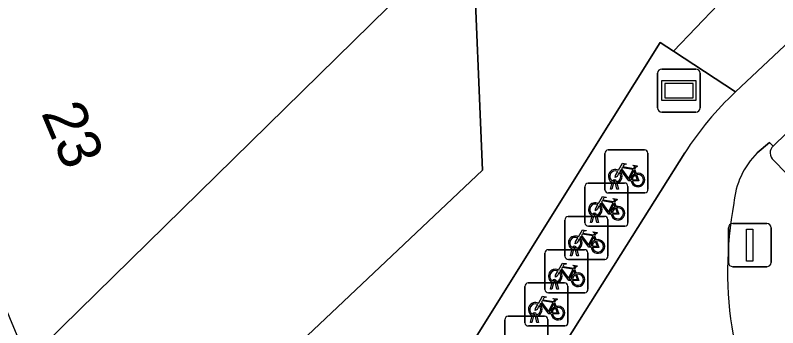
# Model space of a CAD drawing. Extents: x 160663 to 161506, y 382245 to 383291.
# Drawn here: x 161140.59 to 161158.3, y 383139.69 to 383146.96 of the extents above; entities that cross this region are included whole.
import ezdxf

# ---------------------------------------------------------------- set-up
doc = ezdxf.new("R2010")
doc.units = 0
for name, color, linetype in [('IMGEO_Fietsenrek', 7, 'Continuous'), ('IMGEO_Groenvoorziening', 7, 'Continuous'), ('IMGEO_Lichtmast', 7, 'Continuous'), ('IMGEO_Pand', 7, 'Continuous'), ('IMGEO_Pand_nummerreeks', 7, 'Continuous'), ('IMGEO_Parkeervlak_open', 7, 'Continuous'), ('IMGEO_Reclamebord', 7, 'Continuous'), ('IMGEO_Voetpad_open', 7, 'Continuous')]:
    doc.layers.add(name, color=color, linetype=linetype)

msp = doc.modelspace()

# ---------------------------------------------------------------- linework, layer by layer
at = {"layer": 'IMGEO_Fietsenrek'}
for p, q in [((161154.282, 383142.902), (161154.282, 383143.743)), ((161154.282, 383143.743), (161154.282, 383142.902)), ((161154.357, 383143.827), (161155.198, 383143.827)), ((161155.198, 383143.827), (161154.357, 383143.827)), ((161155.282, 383143.752), (161155.282, 383142.911)), ((161155.282, 383142.911), (161155.282, 383143.752)), ((161154.969, 383143.376), (161155.005, 383143.281)), ((161153.818, 383142.129), (161153.818, 383142.97)), ((161153.818, 383142.97), (161153.818, 383142.129)), ((161153.893, 383143.054), (161154.734, 383143.054)), ((161154.734, 383143.054), (161153.893, 383143.054)), ((161154.409, 383142.911), (161154.448, 383143.071)), ((161154.478, 383143.059), (161154.443, 383142.911)), ((161154.52, 383143.083), (161154.519, 383143.087)), ((161154.561, 383142.911), (161154.527, 383143.053)), ((161154.551, 383143.094), (161154.552, 383143.087)), ((161154.559, 383143.057), (161154.594, 383142.911)), ((161154.818, 383142.979), (161154.818, 383142.138)), ((161154.818, 383142.138), (161154.818, 383142.979)), ((161155.207, 383142.827), (161154.366, 383142.827)), ((161154.366, 383142.827), (161155.207, 383142.827)), ((161154.443, 383142.911), (161154.409, 383142.911)), ((161154.594, 383142.911), (161154.561, 383142.911)), ((161154.505, 383142.603), (161154.541, 383142.508)), ((161153.428, 383142.281), (161154.269, 383142.281)), ((161154.269, 383142.281), (161153.428, 383142.281)), ((161153.945, 383142.138), (161153.984, 383142.298)), ((161154.014, 383142.286), (161153.979, 383142.138)), ((161154.056, 383142.31), (161154.055, 383142.314)), ((161154.097, 383142.138), (161154.063, 383142.28)), ((161154.087, 383142.321), (161154.088, 383142.314)), ((161154.095, 383142.284), (161154.13, 383142.138)), ((161153.353, 383141.356), (161153.353, 383142.197)), ((161153.353, 383142.197), (161153.353, 383141.356)), ((161153.979, 383142.138), (161153.945, 383142.138)), ((161154.13, 383142.138), (161154.097, 383142.138)), ((161154.353, 383142.206), (161154.353, 383141.365)), ((161154.353, 383141.365), (161154.353, 383142.206)), ((161154.743, 383142.054), (161153.902, 383142.054)), ((161153.902, 383142.054), (161154.743, 383142.054)), ((161154.04, 383141.83), (161154.076, 383141.735)), ((161153.591, 383141.537), (161153.59, 383141.541)), ((161153.622, 383141.548), (161153.623, 383141.541)), ((161152.889, 383140.583), (161152.889, 383141.424)), ((161152.889, 383141.424), (161152.889, 383140.583)), ((161152.964, 383141.508), (161153.805, 383141.508)), ((161153.805, 383141.508), (161152.964, 383141.508)), ((161153.48, 383141.365), (161153.519, 383141.525)), ((161153.514, 383141.365), (161153.48, 383141.365)), ((161153.549, 383141.513), (161153.514, 383141.365)), ((161153.632, 383141.365), (161153.598, 383141.507)), ((161153.63, 383141.511), (161153.665, 383141.365)), ((161153.665, 383141.365), (161153.632, 383141.365)), ((161153.889, 383141.433), (161153.889, 383140.592)), ((161153.889, 383140.592), (161153.889, 383141.433)), ((161154.278, 383141.281), (161153.437, 383141.281)), ((161153.437, 383141.281), (161154.278, 383141.281)), ((161153.576, 383141.057), (161153.612, 383140.962)), ((161152.424, 383139.81), (161152.424, 383140.651)), ((161152.424, 383140.651), (161152.424, 383139.81)), ((161152.499, 383140.735), (161153.34, 383140.735)), ((161153.34, 383140.735), (161152.499, 383140.735)), ((161153.016, 383140.592), (161153.055, 383140.752)), ((161153.085, 383140.74), (161153.05, 383140.592)), ((161153.127, 383140.764), (161153.126, 383140.768)), ((161153.168, 383140.592), (161153.134, 383140.734)), ((161153.158, 383140.775), (161153.159, 383140.768)), ((161153.166, 383140.738), (161153.201, 383140.592)), ((161153.424, 383140.66), (161153.424, 383139.819)), ((161153.424, 383139.819), (161153.424, 383140.66)), ((161153.814, 383140.508), (161152.973, 383140.508)), ((161152.973, 383140.508), (161153.814, 383140.508)), ((161153.05, 383140.592), (161153.016, 383140.592)), ((161153.201, 383140.592), (161153.168, 383140.592)), ((161153.111, 383140.284), (161153.147, 383140.189)), ((161152.035, 383139.962), (161152.876, 383139.962)), ((161152.876, 383139.962), (161152.035, 383139.962)), ((161152.551, 383139.819), (161152.59, 383139.979)), ((161152.62, 383139.967), (161152.585, 383139.819)), ((161152.662, 383139.991), (161152.661, 383139.995)), ((161152.703, 383139.819), (161152.669, 383139.961)), ((161152.693, 383140.002), (161152.694, 383139.995)), ((161152.701, 383139.965), (161152.736, 383139.819)), ((161151.96, 383139.037), (161151.96, 383139.878)), ((161151.96, 383139.878), (161151.96, 383139.037)), ((161152.585, 383139.819), (161152.551, 383139.819)), ((161152.736, 383139.819), (161152.703, 383139.819)), ((161152.96, 383139.887), (161152.96, 383139.046)), ((161152.96, 383139.046), (161152.96, 383139.887)), ((161153.349, 383139.735), (161152.508, 383139.735)), ((161152.508, 383139.735), (161153.349, 383139.735))]:
    msp.add_line(p, q, dxfattribs=at)
for points in [[(161154.595, 383143.353), (161154.69, 383143.517), (161154.776, 383143.503), (161154.778, 383143.494), (161154.722, 383143.483), (161154.695, 383143.438), (161154.951, 383143.397)], [(161154.616, 383143.301), (161154.564, 383143.211), (161154.524, 383143.186), (161154.525, 383143.233), (161154.58, 383143.327)], [(161154.891, 383143.109), (161154.841, 383143.109), (161154.65, 383143.36), (161154.631, 383143.328)], [(161154.938, 383143.372), (161154.681, 383143.413), (161154.664, 383143.384), (161154.831, 383143.164), (161154.938, 383143.372)], [(161154.986, 383143.274), (161154.956, 383143.351), (161154.847, 383143.133), (161154.89, 383143.133)], [(161154.951, 383143.397), (161154.976, 383143.446), (161154.97, 383143.45), (161154.947, 383143.454), (161154.935, 383143.461), (161154.934, 383143.464), (161154.936, 383143.469), (161155.031, 383143.454), (161155.033, 383143.444), (161155.023, 383143.431), (161155.011, 383143.425), (161154.997, 383143.431), (161154.969, 383143.376)], [(161154.92, 383143.133), (161155.04, 383143.132), (161154.996, 383143.246)], [(161155.016, 383143.253), (161155.071, 383143.108), (161154.921, 383143.108)], [(161154.131, 383142.58), (161154.226, 383142.744), (161154.312, 383142.73), (161154.314, 383142.721), (161154.258, 383142.71), (161154.231, 383142.665), (161154.487, 383142.624)], [(161154.474, 383142.599), (161154.217, 383142.64), (161154.2, 383142.611), (161154.367, 383142.391), (161154.474, 383142.599)], [(161154.487, 383142.624), (161154.512, 383142.673), (161154.506, 383142.677), (161154.483, 383142.681), (161154.471, 383142.688), (161154.47, 383142.691), (161154.472, 383142.696), (161154.567, 383142.681), (161154.569, 383142.671), (161154.559, 383142.658), (161154.547, 383142.652), (161154.533, 383142.658), (161154.505, 383142.603)], [(161154.152, 383142.528), (161154.1, 383142.438), (161154.06, 383142.413), (161154.061, 383142.46), (161154.116, 383142.554)], [(161154.427, 383142.336), (161154.377, 383142.336), (161154.186, 383142.587), (161154.167, 383142.555)], [(161154.522, 383142.501), (161154.492, 383142.578), (161154.383, 383142.36), (161154.426, 383142.36)], [(161154.456, 383142.36), (161154.576, 383142.359), (161154.532, 383142.473)], [(161154.552, 383142.48), (161154.607, 383142.335), (161154.457, 383142.335)], [(161153.666, 383141.807), (161153.761, 383141.971), (161153.847, 383141.957), (161153.849, 383141.948), (161153.793, 383141.937), (161153.766, 383141.892), (161154.022, 383141.851)], [(161154.022, 383141.851), (161154.047, 383141.9), (161154.041, 383141.904), (161154.018, 383141.908), (161154.006, 383141.915), (161154.005, 383141.918), (161154.007, 383141.923), (161154.102, 383141.908), (161154.104, 383141.898), (161154.094, 383141.885), (161154.082, 383141.879), (161154.068, 383141.885), (161154.04, 383141.83)], [(161153.687, 383141.755), (161153.635, 383141.665), (161153.595, 383141.64), (161153.596, 383141.687), (161153.651, 383141.781)], [(161153.962, 383141.563), (161153.912, 383141.563), (161153.721, 383141.814), (161153.702, 383141.782)], [(161154.009, 383141.826), (161153.752, 383141.867), (161153.735, 383141.838), (161153.902, 383141.618), (161154.009, 383141.826)], [(161154.057, 383141.728), (161154.027, 383141.805), (161153.918, 383141.587), (161153.961, 383141.587)], [(161154.087, 383141.707), (161154.142, 383141.562), (161153.992, 383141.562)], [(161153.991, 383141.587), (161154.111, 383141.586), (161154.067, 383141.7)], [(161153.202, 383141.034), (161153.297, 383141.198), (161153.383, 383141.184), (161153.385, 383141.175), (161153.329, 383141.164), (161153.302, 383141.119), (161153.558, 383141.078)], [(161153.223, 383140.982), (161153.171, 383140.892), (161153.131, 383140.867), (161153.132, 383140.914), (161153.187, 383141.008)], [(161153.498, 383140.79), (161153.448, 383140.79), (161153.257, 383141.041), (161153.238, 383141.009)], [(161153.545, 383141.053), (161153.288, 383141.094), (161153.271, 383141.065), (161153.438, 383140.845), (161153.545, 383141.053)], [(161153.593, 383140.955), (161153.563, 383141.032), (161153.454, 383140.814), (161153.497, 383140.814)], [(161153.558, 383141.078), (161153.583, 383141.127), (161153.577, 383141.131), (161153.554, 383141.135), (161153.542, 383141.142), (161153.541, 383141.145), (161153.543, 383141.15), (161153.638, 383141.135), (161153.64, 383141.125), (161153.63, 383141.112), (161153.618, 383141.106), (161153.604, 383141.112), (161153.576, 383141.057)], [(161153.527, 383140.814), (161153.647, 383140.813), (161153.603, 383140.927)], [(161153.623, 383140.934), (161153.678, 383140.789), (161153.528, 383140.789)], [(161152.737, 383140.261), (161152.832, 383140.425), (161152.918, 383140.411), (161152.92, 383140.402), (161152.864, 383140.391), (161152.837, 383140.346), (161153.093, 383140.305)], [(161153.08, 383140.28), (161152.823, 383140.321), (161152.806, 383140.292), (161152.973, 383140.072), (161153.08, 383140.28)], [(161153.093, 383140.305), (161153.118, 383140.354), (161153.112, 383140.358), (161153.089, 383140.362), (161153.077, 383140.369), (161153.076, 383140.372), (161153.078, 383140.377), (161153.173, 383140.362), (161153.175, 383140.352), (161153.165, 383140.339), (161153.153, 383140.333), (161153.139, 383140.339), (161153.111, 383140.284)], [(161152.758, 383140.209), (161152.706, 383140.119), (161152.666, 383140.094), (161152.667, 383140.141), (161152.722, 383140.235)], [(161153.033, 383140.017), (161152.983, 383140.017), (161152.792, 383140.268), (161152.773, 383140.236)], [(161153.128, 383140.182), (161153.098, 383140.259), (161152.989, 383140.041), (161153.032, 383140.041)], [(161153.062, 383140.041), (161153.182, 383140.04), (161153.138, 383140.154)], [(161153.158, 383140.161), (161153.213, 383140.016), (161153.063, 383140.016)]]:
    msp.add_lwpolyline(points, dxfattribs=at)
for centre, radius, start, end in [((161154.36, 383143.749), 0.0779, 92.4484, 184.2845), ((161154.36, 383143.749), 0.0779, 92.4484, 184.2845), ((161155.204, 383143.749), 0.0779, 2.4484, 94.2845), ((161155.204, 383143.749), 0.0779, 2.4484, 94.2845), ((161154.522, 383143.212), 0.159, 62.6766, 242.1369), ((161154.522, 383143.212), 0.129, 63.3192, 238.903), ((161154.522, 383143.212), 0.129, 283.6043, 43.4302), ((161154.522, 383143.212), 0.159, 283.5766, 46.6042), ((161154.502, 383143.083), 0.0499, 12.8025, 158.6934), ((161155.049, 383143.128), 0.159, 113.3408, 178.3217), ((161155.049, 383143.128), 0.159, 187.0065, 105.7708), ((161155.049, 383143.128), 0.129, 113.923, 177.9556), ((161155.049, 383143.128), 0.129, 188.6715, 104.5883), ((161153.896, 383142.976), 0.0779, 92.4484, 184.2845), ((161153.896, 383142.976), 0.0779, 92.4484, 184.2845), ((161154.522, 383143.212), 0.159, 253.9967, 271.7867), ((161154.502, 383143.083), 0.0174, 12.8025, 163.4502), ((161154.522, 383143.212), 0.129, 253.415, 269.0204), ((161154.74, 383142.976), 0.0779, 2.4484, 94.2845), ((161154.74, 383142.976), 0.0779, 2.4484, 94.2845), ((161154.36, 383142.905), 0.0779, 182.4484, 274.2845), ((161154.36, 383142.905), 0.0779, 182.4484, 274.2845), ((161155.204, 383142.905), 0.0779, 272.4484, 4.2845), ((161155.204, 383142.905), 0.0779, 272.4484, 4.2845), ((161154.058, 383142.439), 0.159, 62.6766, 242.1369), ((161154.058, 383142.439), 0.129, 63.3192, 238.903), ((161154.058, 383142.439), 0.129, 283.6043, 43.4302), ((161154.058, 383142.439), 0.159, 283.5766, 46.6042), ((161154.585, 383142.355), 0.159, 113.3408, 178.3217), ((161154.585, 383142.355), 0.159, 187.0065, 105.7708), ((161154.585, 383142.355), 0.129, 113.923, 177.9556), ((161154.585, 383142.355), 0.129, 188.6715, 104.5883), ((161153.431, 383142.203), 0.0779, 92.4484, 184.2845), ((161153.431, 383142.203), 0.0779, 92.4484, 184.2845), ((161154.038, 383142.31), 0.0499, 12.8025, 158.6934), ((161154.058, 383142.439), 0.159, 253.9967, 271.7867), ((161154.038, 383142.31), 0.0174, 12.8025, 163.4502), ((161154.058, 383142.439), 0.129, 253.415, 269.0204), ((161154.275, 383142.203), 0.0779, 2.4484, 94.2845), ((161154.275, 383142.203), 0.0779, 2.4484, 94.2845), ((161153.896, 383142.132), 0.0779, 182.4484, 274.2845), ((161153.896, 383142.132), 0.0779, 182.4484, 274.2845), ((161154.74, 383142.132), 0.0779, 272.4484, 4.2845), ((161154.74, 383142.132), 0.0779, 272.4484, 4.2845), ((161153.593, 383141.666), 0.159, 62.6766, 242.1369), ((161153.593, 383141.666), 0.129, 63.3192, 238.903), ((161153.593, 383141.666), 0.129, 283.6043, 43.4302), ((161153.593, 383141.666), 0.159, 283.5766, 46.6042), ((161154.12, 383141.582), 0.159, 113.3408, 178.3217), ((161154.12, 383141.582), 0.159, 187.0065, 105.7708), ((161154.12, 383141.582), 0.129, 188.6715, 104.5883), ((161153.573, 383141.537), 0.0499, 12.8025, 158.6934), ((161153.573, 383141.537), 0.0174, 12.8025, 163.4502), ((161153.593, 383141.666), 0.129, 253.415, 269.0204), ((161154.12, 383141.582), 0.129, 113.923, 177.9556), ((161152.967, 383141.43), 0.0779, 92.4484, 184.2845), ((161152.967, 383141.43), 0.0779, 92.4484, 184.2845), ((161153.431, 383141.359), 0.0779, 182.4484, 274.2845), ((161153.431, 383141.359), 0.0779, 182.4484, 274.2845), ((161153.593, 383141.666), 0.159, 253.9967, 271.7867), ((161153.811, 383141.43), 0.0779, 2.4484, 94.2845), ((161153.811, 383141.43), 0.0779, 2.4484, 94.2845), ((161154.275, 383141.359), 0.0779, 272.4484, 4.2845), ((161154.275, 383141.359), 0.0779, 272.4484, 4.2845), ((161153.129, 383140.893), 0.159, 62.6766, 242.1369), ((161153.129, 383140.893), 0.129, 63.3192, 238.903), ((161153.129, 383140.893), 0.159, 283.5766, 46.6042), ((161153.129, 383140.893), 0.129, 283.6043, 43.4302), ((161153.656, 383140.809), 0.159, 113.3408, 178.3217), ((161153.656, 383140.809), 0.159, 187.0065, 105.7708), ((161153.656, 383140.809), 0.129, 113.923, 177.9556), ((161153.656, 383140.809), 0.129, 188.6715, 104.5883), ((161152.502, 383140.657), 0.0779, 92.4484, 184.2845), ((161152.502, 383140.657), 0.0779, 92.4484, 184.2845), ((161153.109, 383140.764), 0.0499, 12.8025, 158.6934), ((161153.129, 383140.893), 0.159, 253.9967, 271.7867), ((161153.109, 383140.764), 0.0174, 12.8025, 163.4502), ((161153.129, 383140.893), 0.129, 253.415, 269.0204), ((161153.346, 383140.657), 0.0779, 2.4484, 94.2845), ((161153.346, 383140.657), 0.0779, 2.4484, 94.2845), ((161152.967, 383140.586), 0.0779, 182.4484, 274.2845), ((161152.967, 383140.586), 0.0779, 182.4484, 274.2845), ((161153.811, 383140.586), 0.0779, 272.4484, 4.2845), ((161153.811, 383140.586), 0.0779, 272.4484, 4.2845), ((161152.664, 383140.12), 0.159, 62.6766, 242.1369), ((161152.664, 383140.12), 0.129, 63.3192, 238.903), ((161152.664, 383140.12), 0.129, 283.6043, 43.4302), ((161152.664, 383140.12), 0.159, 283.5766, 46.6042), ((161153.191, 383140.036), 0.159, 113.3408, 178.3217), ((161153.191, 383140.036), 0.159, 187.0065, 105.7708), ((161153.191, 383140.036), 0.129, 113.923, 177.9556), ((161153.191, 383140.036), 0.129, 188.6715, 104.5883), ((161152.038, 383139.884), 0.0779, 92.4484, 184.2845), ((161152.038, 383139.884), 0.0779, 92.4484, 184.2845), ((161152.644, 383139.991), 0.0499, 12.8025, 158.6934), ((161152.664, 383140.12), 0.159, 253.9967, 271.7867), ((161152.644, 383139.991), 0.0174, 12.8025, 163.4502), ((161152.664, 383140.12), 0.129, 253.415, 269.0204), ((161152.882, 383139.884), 0.0779, 2.4484, 94.2845), ((161152.882, 383139.884), 0.0779, 2.4484, 94.2845), ((161152.502, 383139.813), 0.0779, 182.4484, 274.2845), ((161152.502, 383139.813), 0.0779, 182.4484, 274.2845), ((161153.346, 383139.813), 0.0779, 272.4484, 4.2845), ((161153.346, 383139.813), 0.0779, 272.4484, 4.2845)]:
    msp.add_arc(centre, radius, start, end, dxfattribs=at)
at = {"layer": 'IMGEO_Groenvoorziening'}
for points in [[(161159.601, 383161.046), (161156.987, 383162.473), (161154.786, 383163.643), (161151.498, 383165.39), (161151.378, 383165.212), (161146.783, 383158.104), (161149.389, 383151.959), (161150.771, 383148.7), (161150.848, 383148.779), (161151.214, 383148.74), (161151.442, 383143.355), (161142.883, 383135.27), (161146.227, 383132.301), (161147.528, 383133.493), (161149.889, 383137.24), (161153.216, 383142.573), (161155.564, 383146.324), (161155.876, 383146.12), (161165.215, 383155.885)], [(161166.528, 383154.573), (161166.335, 383154.758), (161165.215, 383155.885), (161155.876, 383146.12), (161157.319, 383145.175), (161162.383, 383149.949), (161166.424, 383153.804)], [(161158.189, 383143.914), (161158.107, 383144), (161157.821, 383143.755)], [(161173.591, 383127.787), (161158.2, 383143.585)]]:
    msp.add_lwpolyline(points, dxfattribs=at)
for centre, radius, start, end in [((161158.34, 383143.754), 0.22, 133.3488, 230.4811), ((161159.102, 383142.451), 1.828, 134.4903, 175.7606), ((161165.782, 383141.002), 8.65, 169.446, 189.8432)]:
    msp.add_arc(centre, radius, start, end, dxfattribs=at)
at = {"layer": 'IMGEO_Lichtmast'}
for p, q in [((161157.25, 383142.113), (161158.04, 383142.113)), ((161158.04, 383142.113), (161157.25, 383142.113)), ((161157.15, 383141.213), (161157.15, 383142.013)), ((161157.15, 383142.013), (161157.15, 383141.213)), ((161158.14, 383142.013), (161158.14, 383141.213)), ((161158.14, 383141.213), (161158.14, 383142.013)), ((161158.04, 383141.113), (161157.25, 383141.113)), ((161157.25, 383141.113), (161158.04, 383141.113))]:
    msp.add_line(p, q, dxfattribs=at)
msp.add_lwpolyline([(161157.57, 383141.988), (161157.72, 383141.988), (161157.72, 383141.238), (161157.57, 383141.238), (161157.57, 383141.988)], dxfattribs=at)
for centre, start, end in [((161157.25, 383142.013), 90, 180), ((161157.25, 383142.013), 90, 180), ((161158.04, 383142.013), 0, 90), ((161158.04, 383142.013), 360, 90), ((161157.25, 383141.213), 180, 270), ((161157.25, 383141.213), 180, 270), ((161158.04, 383141.213), 270, 0), ((161158.04, 383141.213), 270, 0)]:
    msp.add_arc(centre, 0.1, start, end, dxfattribs=at)
at = {"layer": 'IMGEO_Pand'}
msp.add_lwpolyline([(161147.876, 383150.976), (161137.518, 383146.979), (161140.874, 383138.924), (161149.641, 383147.54)], close=True, dxfattribs=at)
at = {"layer": 'IMGEO_Parkeervlak_open'}
msp.add_lwpolyline([(161151.442, 383143.355), (161151.214, 383148.74), (161150.848, 383148.779), (161150.771, 383148.7), (161151.034, 383148.078), (161149.641, 383147.54), (161140.874, 383138.924), (161141.404, 383136.895), (161142.883, 383135.27)], close=True, dxfattribs=at)
for points in [[(161161.604, 383147.241), (161158.189, 383143.914)], [(161158.2, 383143.585), (161173.591, 383127.787)]]:
    msp.add_lwpolyline(points, dxfattribs=at)
msp.add_arc((161158.34, 383143.754), 0.22, 133.3488, 230.4811, dxfattribs=at)
at = {"layer": 'IMGEO_Reclamebord'}
for p, q in [((161155.505, 383144.806), (161155.505, 383145.606)), ((161155.505, 383145.606), (161155.505, 383144.806)), ((161155.605, 383145.706), (161156.395, 383145.706)), ((161156.395, 383145.706), (161155.605, 383145.706)), ((161156.495, 383145.606), (161156.495, 383144.806)), ((161156.495, 383144.806), (161156.495, 383145.606)), ((161156.395, 383144.706), (161155.605, 383144.706)), ((161155.605, 383144.706), (161156.395, 383144.706))]:
    msp.add_line(p, q, dxfattribs=at)
for points in [[(161155.606, 383145.438), (161156.394, 383145.438), (161156.394, 383144.974), (161155.606, 383144.974), (161155.606, 383145.438)], [(161155.671, 383145.373), (161155.671, 383145.039), (161156.329, 383145.039), (161156.329, 383145.373), (161155.671, 383145.373)]]:
    msp.add_lwpolyline(points, dxfattribs=at)
for centre, start, end in [((161155.605, 383145.606), 90, 180), ((161155.605, 383145.606), 90, 180), ((161156.395, 383145.606), 0, 90), ((161156.395, 383145.606), 360, 90), ((161155.605, 383144.806), 180, 270), ((161155.605, 383144.806), 180, 270), ((161156.395, 383144.806), 270, 0), ((161156.395, 383144.806), 270, 0)]:
    msp.add_arc(centre, 0.1, start, end, dxfattribs=at)
at = {"layer": 'IMGEO_Voetpad_open'}
for points in [[(161157.821, 383143.755), (161158.107, 383144), (161158.189, 383143.914), (161161.604, 383147.241), (161163.367, 383148.958), (161167.828, 383153.324), (161166.528, 383154.573)], [(161166.424, 383153.804), (161162.383, 383149.949), (161157.319, 383145.175)], [(161157.319, 383145.175), (161155.876, 383146.12), (161155.564, 383146.324), (161153.216, 383142.573), (161149.889, 383137.24), (161147.528, 383133.493), (161146.227, 383132.301), (161148.063, 383130.922), (161156.139, 383143.756)], [(161156.139, 383143.756), (161148.063, 383130.922), (161150.195, 383129.36), (161152.279, 383127.837), (161154.752, 383130.355)]]:
    msp.add_lwpolyline(points, dxfattribs=at)
for centre, radius, start, end in [((161162.261, 383139.865), 7.254, 132.9454, 147.5627), ((161162.261, 383139.865), 7.254, 132.9454, 147.5627), ((161159.102, 383142.451), 1.828, 134.4903, 175.7606), ((161165.782, 383141.002), 8.65, 169.446, 189.8432)]:
    msp.add_arc(centre, radius, start, end, dxfattribs=at)

# ---------------------------------------------------------------- texts
at = {"layer": 'IMGEO_Pand_nummerreeks'}
msp.add_text('23', height=1, rotation=292.8454, dxfattribs=at).set_placement((161141.181, 383144.685))

doc.saveas('drawing.dxf')
